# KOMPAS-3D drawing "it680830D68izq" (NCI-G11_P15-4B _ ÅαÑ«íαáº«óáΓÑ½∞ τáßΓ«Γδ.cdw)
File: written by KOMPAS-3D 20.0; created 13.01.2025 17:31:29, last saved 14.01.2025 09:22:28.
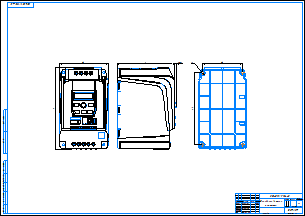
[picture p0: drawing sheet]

Sheet 1: A1, landscape

Document properties: Полное имя файла: P:\INSTART\Технический отдел\ОР\Прочие задачи\КД на номенклатурный ряд\КД на типоразмеры ПЧ\NCI\NCI-G11_P15-4B\NCI-G11_P15-4B _ Преобразователь частоты.cdw; Автор: admin

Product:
- Part/product: it680830D68izq

Title block, sheet 1: Наименование: Преобразователь / частоты; designation: NCI-G11/P15-4B; Количество листов документа: 1; organisation: INSTART; cell 10: Согласовано; Форматы листов документа: A1; Разработал: Уралов Д.А.; Проверил: Андреев Н.В.; Подписал: Смелков Ж.Е.; Утвердил: Ефремов И.Н.; Разработал, date: 13.01.25

Referenced files in C:\Уралов Работа\Уралов (локальная)\ПЧ\! Китай 3Д-модель NCI\NCI 11-15 4B\: NCI 11-15 4B.m3d
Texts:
  Поверхности
  it680830D68izq
  it680830D68izq it680830D68izq
Dimensions and other numbers on the sheet: 1:1; 1; 13.01.25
